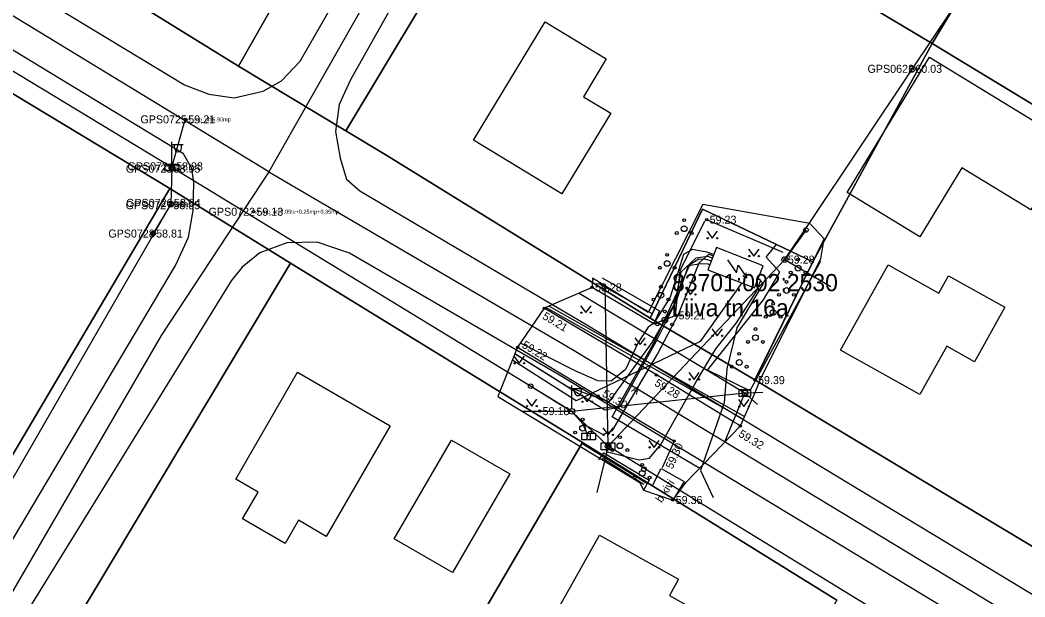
# Model space of a CAD drawing. Extents: x 580119 to 583377, y 6518915 to 6520820.
# Drawn here: x 581772.7 to 581860.5, y 6520226.6 to 6520277 of the extents above; entities that cross this region are included whole.
import ezdxf

# ---------------------------------------------------------------- set-up
doc = ezdxf.new("R2010")
doc.units = 0
for name, color, linetype in [('AED', 7, 'Continuous'), ('ELRAJATISMP', 7, 'Continuous'), ('HALJASTUS', 7, 'Continuous'), ('HOONE', 7, 'Continuous'), ('Hoone Elu- või ühiskondlik hoone', 7, 'Continuous'), ('Hoone Kõrval- või tootmishoone', 7, 'Continuous'), ('KORGUS-EH2000', 7, 'Continuous'), ('KPKAABEL', 7, 'Continuous'), ('KTRASS', 7, 'Continuous'), ('L_AADRESS', 7, 'Continuous'), ('MAAMUDEL', 7, 'Continuous'), ('MOOTKORG-EH2000', 7, 'Continuous'), ('MOOTMPUNKT', 7, 'Continuous'), ('MOOTNR', 7, 'Continuous'), ('MOOTPIIR', 7, 'Continuous'), ('MPKAABEL', 7, 'Continuous'), ('MPOHULIIN', 7, 'Continuous'), ('PIIR', 7, 'Continuous'), ('POST', 7, 'Continuous'), ('PUU', 7, 'Continuous'), ('RAJATIS', 7, 'Continuous'), ('Rippe kõrgus', 7, 'Continuous'), ('SIOHULIIN', 7, 'Continuous'), ('SIRAJATIS', 7, 'Continuous'), ('TEE', 7, 'Continuous'), ('Tee Liiklusala', 7, 'Continuous'), ('Tee Tänav Püsikate', 7, 'Continuous'), ('TUNNUS', 7, 'Continuous'), ('VTRASS', 7, 'Continuous')]:
    doc.layers.add(name, color=color, linetype=linetype)

msp = doc.modelspace()

# ---------------------------------------------------------------- linework, layer by layer
at = {"layer": 'AED'}
msp.add_line((581827.466, 6520236.498), (581821.792, 6520239.985), dxfattribs=at)
for points in [[(581839.378, 6520256.69), (581832.693, 6520259.554)], [(581836.922, 6520245.539), (581840.548, 6520252.925), (581842.98, 6520257.886)]]:
    msp.add_lwpolyline(points, dxfattribs=at)
at = {"layer": 'ELRAJATISMP'}
for p, q in [((581785.791, 6520264.412), (581785.791, 6520263.816)), ((581786.063, 6520264.412), (581786.063, 6520263.816)), ((581822.227, 6520240.919), (581822.227, 6520240.322)), ((581822.499, 6520240.919), (581822.499, 6520240.322)), ((581823.935, 6520240.058), (581823.935, 6520239.461)), ((581824.206, 6520240.058), (581824.206, 6520239.461))]:
    msp.add_line(p, q, dxfattribs=at)
for points in [[(581785.33, 6520264.412), (581786.524, 6520264.412), (581786.524, 6520263.816), (581785.33, 6520263.816)], [(581821.766, 6520240.919), (581822.96, 6520240.919), (581822.96, 6520240.322), (581821.766, 6520240.322)], [(581823.473, 6520240.058), (581824.668, 6520240.058), (581824.668, 6520239.461), (581823.473, 6520239.461)]]:
    msp.add_lwpolyline(points, close=True, dxfattribs=at)
at = {"layer": 'HALJASTUS'}
for p, q in [((581832.722, 6520258.54), (581833.185, 6520257.933)), ((581833.185, 6520257.933), (581833.631, 6520258.54)), ((581836.362, 6520256.984), (581836.825, 6520256.377)), ((581836.825, 6520256.377), (581837.271, 6520256.984)), ((581828.083, 6520250.471), (581822.67, 6520253.641)), ((581827.982, 6520251.297), (581823.284, 6520253.95)), ((581830.823, 6520253.633), (581831.286, 6520253.026)), ((581831.286, 6520253.026), (581831.732, 6520253.633)), ((581821.671, 6520252.042), (581822.134, 6520251.435)), ((581822.134, 6520251.435), (581822.58, 6520252.042)), ((581833.155, 6520250.026), (581833.618, 6520249.419)), ((581833.618, 6520249.419), (581834.064, 6520250.026)), ((581826.406, 6520249.248), (581826.869, 6520248.641)), ((581826.869, 6520248.641), (581827.315, 6520249.248)), ((581815.84, 6520247.621), (581816.304, 6520247.015)), ((581816.304, 6520247.015), (581816.749, 6520247.621)), ((581831.141, 6520246.207), (581831.604, 6520245.6)), ((581831.604, 6520245.6), (581832.05, 6520246.207)), ((581816.936, 6520243.873), (581817.399, 6520243.266)), ((581817.399, 6520243.266), (581817.845, 6520243.873)), ((581821.777, 6520244.262), (581822.24, 6520243.655)), ((581822.24, 6520243.655), (581822.686, 6520244.262)), ((581835.487, 6520243.838), (581835.95, 6520243.231)), ((581835.95, 6520243.231), (581836.396, 6520243.838)), ((581823.614, 6520241.362), (581824.078, 6520240.756)), ((581824.078, 6520240.756), (581824.523, 6520241.362)), ((581827.642, 6520240.266), (581828.106, 6520239.659)), ((581828.106, 6520239.659), (581828.551, 6520240.266)), ((581827.199, 6520236.43), (581823.552, 6520238.734))]:
    msp.add_line(p, q, dxfattribs=at)
for points in [[(581828.083, 6520250.471), (581829.976, 6520251.196), (581830.373, 6520255.128), (581832.537, 6520259.46)], [(581842.643, 6520255.917), (581836.47, 6520244.601), (581832.774, 6520246.407), (581837.658, 6520252.565), (581839.089, 6520254.972), (581837.891, 6520256.288), (581838.778, 6520257.354)], [(581823.56, 6520254.485), (581828.564, 6520251.599), (581828.083, 6520250.471)], [(581823.261, 6520238.588), (581823.694, 6520239.187), (581827.667, 6520236.798), (581827.164, 6520235.94)]]:
    msp.add_lwpolyline(points, dxfattribs=at)
for centre in [(581832.784, 6520257.933), (581833.613, 6520257.933), (581836.424, 6520256.377), (581837.253, 6520256.377), (581830.885, 6520253.026), (581831.714, 6520253.026), (581821.733, 6520251.435), (581822.562, 6520251.435), (581833.217, 6520249.419), (581834.046, 6520249.419), (581826.468, 6520248.641), (581827.297, 6520248.641), (581815.903, 6520247.015), (581816.731, 6520247.015), (581831.203, 6520245.6), (581832.032, 6520245.6), (581816.998, 6520243.266), (581817.827, 6520243.266), (581821.839, 6520243.655), (581822.668, 6520243.655), (581835.549, 6520243.231), (581836.378, 6520243.231), (581823.677, 6520240.756), (581824.505, 6520240.756), (581827.705, 6520239.659), (581828.534, 6520239.659)]:
    msp.add_circle(centre, 0.055, dxfattribs=at)
at = {"layer": 'HOONE'}
for p, q in [((581834.528, 6520256.055), (581835.296, 6520254.925)), ((581835.296, 6520254.925), (581835.439, 6520255.595)), ((581835.439, 6520255.595), (581836.203, 6520254.483)), ((581835.864, 6520254.689), (581836.203, 6520254.483)), ((581836.203, 6520254.483), (581836.148, 6520254.903))]:
    msp.add_line(p, q, dxfattribs=at)
at = {"layer": 'Hoone Elu- või ühiskondlik hoone'}
for points in [[(581824.303, 6520268.845), (581820.036, 6520261.801), (581812.298, 6520266.488), (581818.564, 6520276.833), (581823.908, 6520273.596), (581821.909, 6520270.295)], [(581848.562, 6520255.598), (581852.99, 6520253.13), (581853.842, 6520254.658), (581858.765, 6520251.913), (581856.109, 6520247.148), (581853.689, 6520248.497), (581851.338, 6520244.28), (581844.406, 6520248.144)], [(581805.018, 6520241.546), (581799.427, 6520231.891), (581796.996, 6520233.293), (581795.82, 6520231.264), (581792.106, 6520233.418), (581793.467, 6520235.767), (581791.514, 6520236.901), (581796.918, 6520246.233)], [(581836.336, 6520222.854), (581831.118, 6520213.557), (581817.32, 6520221.3), (581823.333, 6520232.009), (581830.215, 6520228.148), (581829.428, 6520226.73)]]:
    msp.add_lwpolyline(points, close=True, dxfattribs=at)
at = {"layer": 'Hoone Kõrval- või tootmishoone'}
for points in [[(581864.55, 6520266.195), (581861.03, 6520260.418), (581855.004, 6520264.091), (581851.329, 6520258.061), (581844.973, 6520261.934), (581852.169, 6520273.74)], [(581805.375, 6520231.681), (581810.374, 6520240.306), (581815.479, 6520237.349), (581810.48, 6520228.726)]]:
    msp.add_lwpolyline(points, close=True, dxfattribs=at)
at = {"layer": 'KORGUS-EH2000'}
for centre in [(581832.693, 6520259.554), (581839.53, 6520256.065), (581822.67, 6520253.641), (581818.485, 6520251.819), (581829.976, 6520251.196), (581816.164, 6520248.415), (581828.301, 6520245.992), (581836.922, 6520245.539), (581823.181, 6520244.154), (581818.085, 6520242.831), (581835.637, 6520241.537), (581829.849, 6520240.211), (581829.725, 6520235.067)]:
    msp.add_circle(centre, 0.1, dxfattribs=at)
at = {"layer": 'KPKAABEL'}
for points in [[(581832.09, 6520237.828), (581824.438, 6520242.332), (581828.156, 6520248.945), (581831.258, 6520255.664), (581832.008, 6520256.121), (581832.594, 6520256.098), (581833.114, 6520255.966)], [(581835.762, 6520254.025), (581832.124, 6520248.9), (581821.294, 6520243.721), (581815.71, 6520247.284)]]:
    msp.add_lwpolyline(points, dxfattribs=at)
at = {"layer": 'KTRASS'}
msp.add_line((581818.912, 6520252.004), (581836, 6520242.348), dxfattribs=at)
at = {"layer": 'MOOTMPUNKT'}
for centre in [(581850.68, 6520272.732), (581787.097, 6520268.317), (581785.822, 6520264.01), (581786.033, 6520264.218), (581785.8, 6520260.82), (581785.844, 6520261.02), (581793.059, 6520260.246), (581784.288, 6520258.342)]:
    msp.add_circle(centre, 0.1, dxfattribs=at)
at = {"layer": 'MOOTPIIR'}
msp.add_lwpolyline([(581822.67, 6520253.641), (581818.485, 6520251.819), (581816.164, 6520248.415), (581814.433, 6520244.097), (581826.858, 6520236.585), (581827.164, 6520235.94), (581829.725, 6520235.067), (581830.914, 6520236.63), (581835.637, 6520241.537), (581836.938, 6520244.448), (581837.461, 6520245.756), (581842.672, 6520256.148), (581842.98, 6520257.886), (581841.725, 6520259.214), (581832.36, 6520260.889), (581827.587, 6520251.444), (581822.704, 6520254.435)], close=True, dxfattribs=at)
at = {"layer": 'MPKAABEL'}
msp.add_line((581821.871, 6520241.723), (581820.901, 6520242.813), dxfattribs=at)
for points in [[(581833.2, 6520256.185), (581832.797, 6520256.348), (581831.754, 6520256.195), (581830.426, 6520254.984), (581829.867, 6520252.203), (581827.906, 6520248.824), (581824.148, 6520243.645), (581820.508, 6520244.957), (581815.93, 6520247.831)], [(581833.329, 6520256.518), (581832.719, 6520256.715), (581831.43, 6520256.953), (581830.664, 6520256.504), (581829.496, 6520252.773), (581828.059, 6520250.527), (581827.57, 6520250.152), (581826.699, 6520248.828), (581825.598, 6520246.465), (581824.328, 6520245.453), (581823.18, 6520245.465), (581821.254, 6520246.32), (581816.41, 6520248.776)], [(581822.363, 6520240.621), (581821.871, 6520241.723), (581823.648, 6520240.801), (581824.453, 6520241.133), (581828.398, 6520247.82), (581830.262, 6520251.371), (581832.039, 6520255.789), (581832.875, 6520256.555), (581833.278, 6520256.388)], [(581815.934, 6520247.84), (581821.098, 6520244.609), (581823.789, 6520242.93), (581825.086, 6520243.203), (581828.262, 6520248.906), (581830.047, 6520252.453), (581831.105, 6520255.547), (581832.172, 6520255.738), (581832.781, 6520255.684), (581832.976, 6520255.608)], [(581837.215, 6520254.426), (581837.621, 6520253.973), (581835.32, 6520250.113), (581834.453, 6520246.527), (581834.234, 6520243.559), (581832.145, 6520237.648), (581833.27, 6520235.277)], [(581824.071, 6520239.759), (581823.906, 6520239.316), (581826.789, 6520238.566), (581827.695, 6520238.734), (581828.688, 6520239.93), (581831.809, 6520245.457), (581833.484, 6520248.273), (581835.297, 6520250.539), (581837.07, 6520253.344), (581837.43, 6520254.273), (581837.191, 6520254.365)]]:
    msp.add_lwpolyline(points, dxfattribs=at)
at = {"layer": 'MPOHULIIN'}
for p, q in [((581785.927, 6520264.114), (581787.097, 6520268.317)), ((581839.53, 6520256.065), (581824.071, 6520239.759)), ((581839.53, 6520256.065), (581843.539, 6520253.717)), ((581824.071, 6520239.759), (581823.805, 6520253.76)), ((581818.085, 6520242.831), (581820.901, 6520242.813)), ((581824.071, 6520239.759), (581820.901, 6520242.813))]:
    msp.add_line(p, q, dxfattribs=at)
for points in [[(581815.289, 6520246.232), (581785.927, 6520264.114), (581748.774, 6520286.579), (581716.955, 6520305.703), (581694.046, 6520319.434)], [(581841.646, 6520259.228), (581850.68, 6520272.732), (581867.762, 6520298.217)], [(581785.927, 6520264.114), (581785.822, 6520260.92), (581761.898, 6520219.504), (581760.006, 6520194.701), (581760.577, 6520193.807)], [(581839.53, 6520256.065), (581841.646, 6520259.228)], [(581820.901, 6520242.813), (581815.289, 6520246.232)], [(581830.36, 6520235.901), (581824.071, 6520239.759), (581823.075, 6520235.724)], [(582074.165, 6520090.199), (582035.134, 6520113.983), (581994.066, 6520138.741), (581958.895, 6520159.666), (581929.453, 6520177.381), (581899.05, 6520195.285), (581871.107, 6520211.349), (581850.55, 6520223.515), (581830.36, 6520235.901)]]:
    msp.add_lwpolyline(points, dxfattribs=at)
at = {"layer": 'PIIR'}
for points in [[(581641.44, 6520358.2), (581663.75, 6520346.68), (581696.78, 6520330.58), (581710.47, 6520322.41), (581741.73, 6520303.41), (581773.45, 6520284.3), (581791.76, 6520272.95), (581801.15, 6520267.32), (581804.72, 6520265.17), (581827.76, 6520250.96), (581836.91, 6520245.57), (581863.22, 6520229.79), (581868.94, 6520226.76), (581900.21, 6520207.51)], [(581844.07, 6520226.32), (581821.83, 6520240.08), (581796.29, 6520255.75), (581785.75, 6520262.28), (581756.8, 6520279.75), (581732.4, 6520294.58), (581704.08, 6520311.14), (581691.15, 6520319.03), (581661.06, 6520334.72)]]:
    msp.add_lwpolyline(points, dxfattribs=at)
for points in [[(581801.15, 6520267.32), (581791.76, 6520272.95), (581808.12, 6520301.74), (581821.48, 6520324.8), (581832.08, 6520318.73), (581818.12, 6520295.6)], [(581788.16, 6520313.33), (581791.12, 6520311.82), (581808.12, 6520301.74), (581791.76, 6520272.95), (581773.45, 6520284.3)], [(581849.2, 6520308.51), (581866.2, 6520297.82), (581852.4, 6520274.95), (581835.18, 6520285.22)], [(581866.2, 6520297.82), (581884.83, 6520286.51), (581870.83, 6520263.78), (581852.4, 6520274.95)], [(581818.12, 6520295.6), (581835.18, 6520285.22), (581852.4, 6520274.95), (581841.97, 6520255.88), (581832.33, 6520260.46), (581827.76, 6520250.96), (581804.72, 6520265.17), (581801.15, 6520267.32)], [(581756.8, 6520279.75), (581785.75, 6520262.28), (581768.66, 6520233.42), (581739.56, 6520251.04)], [(581841.97, 6520255.88), (581852.4, 6520274.95), (581870.83, 6520263.78), (581886.05, 6520254.56), (581863.22, 6520229.79), (581836.91, 6520245.57)], [(581696.38, 6520086.78), (581684.97, 6520093.06), (581699.34, 6520117.41), (581709.83, 6520135.06), (581730.99, 6520170.6), (581750.36, 6520203.28), (581768.66, 6520233.42), (581785.75, 6520262.28), (581796.29, 6520255.75), (581771.2, 6520213.92), (581755.98, 6520188.75), (581745.76, 6520171.44), (581728.54, 6520142.46), (581721.29, 6520129.05)], [(581832.33, 6520260.46), (581841.97, 6520255.88), (581836.91, 6520245.57), (581827.76, 6520250.96)], [(581796.29, 6520255.75), (581821.83, 6520240.08), (581802.53, 6520207.1), (581797.51, 6520198.44), (581771.2, 6520213.92)], [(581821.83, 6520240.08), (581844.07, 6520226.32), (581828.18, 6520198.39), (581825.04, 6520199.93), (581822.65, 6520196.25), (581820.67, 6520197.28), (581802.53, 6520207.1)]]:
    msp.add_lwpolyline(points, close=True, dxfattribs=at)
at = {"layer": 'POST'}
for p, q in [((581785.927, 6520264.364), (581785.927, 6520266.364)), ((581785.927, 6520266.114), (581786.927, 6520266.114)), ((581786.154, 6520265.793), (581786.154, 6520266.114)), ((581786.767, 6520265.793), (581786.767, 6520266.114)), ((581785.927, 6520264.114), (581785.927, 6520264.114)), ((581820.901, 6520243.063), (581820.901, 6520245.063)), ((581820.901, 6520244.813), (581821.901, 6520244.813)), ((581821.128, 6520244.492), (581821.128, 6520244.813)), ((581821.741, 6520244.492), (581821.741, 6520244.813)), ((581820.901, 6520242.813), (581820.901, 6520242.813))]:
    msp.add_line(p, q, dxfattribs=at)
for points in [[(581785.822, 6520260.92), (581784.288, 6520258.342)], [(581841.383, 6520258.655), (581839.53, 6520256.065)], [(581817.303, 6520245.014), (581820.901, 6520242.813)]]:
    msp.add_lwpolyline(points, dxfattribs=at)
for centre, radius in [((581850.68, 6520272.732), 0.25), ((581785.927, 6520264.114), 0.25), ((581785.822, 6520260.92), 0.25), ((581841.383, 6520258.655), 0.2), ((581784.288, 6520258.342), 0.2), ((581839.53, 6520256.065), 0.25), ((581817.303, 6520245.014), 0.2), ((581836.033, 6520244.413), 0.25), ((581820.901, 6520242.813), 0.25), ((581824.071, 6520239.759), 0.25), ((581827.203, 6520237.753), 0.2)]:
    msp.add_circle(centre, radius, dxfattribs=at)
for centre in [(581786.46, 6520265.793), (581821.434, 6520244.492)]:
    msp.add_arc(centre, 0.306, 180, 0, dxfattribs=at)
at = {"layer": 'PUU'}
for centre, radius in [((581830.727, 6520258.766), 0.25), ((581830.727, 6520259.516), 0.125), ((581830.077, 6520258.391), 0.125), ((581831.377, 6520258.391), 0.125), ((581829.242, 6520256.482), 0.125), ((581840.692, 6520256.068), 0.125), ((581828.592, 6520255.357), 0.125), ((581829.242, 6520255.732), 0.25), ((581829.892, 6520255.357), 0.125), ((581840.692, 6520255.318), 0.25), ((581840.042, 6520254.943), 0.125), ((581841.342, 6520254.943), 0.125), ((581828.691, 6520253.702), 0.125), ((581839.674, 6520253.366), 0.25), ((581839.674, 6520254.116), 0.125), ((581828.041, 6520252.577), 0.125), ((581828.691, 6520252.952), 0.25), ((581829.341, 6520252.577), 0.125), ((581839.024, 6520252.991), 0.125), ((581840.324, 6520252.991), 0.125), ((581838.508, 6520252.206), 0.125), ((581829.029, 6520250.772), 0.25), ((581829.029, 6520251.522), 0.125), ((581837.858, 6520251.081), 0.125), ((581838.508, 6520251.456), 0.25), ((581839.158, 6520251.081), 0.125), ((581828.379, 6520250.397), 0.125), ((581829.679, 6520250.397), 0.125), ((581836.96, 6520250), 0.125), ((581836.96, 6520249.25), 0.25), ((581836.31, 6520248.875), 0.125), ((581837.61, 6520248.875), 0.125), ((581835.54, 6520247.835), 0.125), ((581834.89, 6520246.71), 0.125), ((581835.54, 6520247.085), 0.25), ((581836.19, 6520246.71), 0.125), ((581821.841, 6520242.087), 0.125), ((581821.841, 6520241.337), 0.25), ((581821.191, 6520240.962), 0.125), ((581822.491, 6520240.962), 0.125), ((581825.11, 6520240.553), 0.125), ((581824.46, 6520239.428), 0.125), ((581825.11, 6520239.803), 0.25), ((581825.76, 6520239.428), 0.125), ((581827.05, 6520238.146), 0.125), ((581826.4, 6520237.021), 0.125), ((581827.05, 6520237.396), 0.25), ((581827.7, 6520237.021), 0.125)]:
    msp.add_circle(centre, radius, dxfattribs=at)
at = {"layer": 'RAJATIS'}
msp.add_lwpolyline([(581832.806, 6520255.173), (581836.889, 6520253.587), (581837.646, 6520255.534), (581833.563, 6520257.12)], close=True, dxfattribs=at)
at = {"layer": 'SIOHULIIN'}
msp.add_line((581836.033, 6520244.413), (581821.546, 6520253.116), dxfattribs=at)
for points in [[(581837.59, 6520244.473), (581836.033, 6520244.413), (581820.901, 6520242.813), (581816.592, 6520242.794)], [(581834.293, 6520240.141), (581836.033, 6520244.413), (581837.142, 6520243.397)]]:
    msp.add_lwpolyline(points, dxfattribs=at)
at = {"layer": 'SIRAJATIS'}
msp.add_lwpolyline([(581835.533, 6520244.713), (581836.533, 6520244.713), (581836.533, 6520244.113), (581835.533, 6520244.113)], close=True, dxfattribs=at)
for centre, radius in [((581835.833, 6520244.413), 0.0304), ((581835.833, 6520244.413), 0.029), ((581835.833, 6520244.413), 0.0277), ((581835.833, 6520244.413), 0.0263), ((581835.833, 6520244.413), 0.0249), ((581835.833, 6520244.413), 0.0236), ((581835.833, 6520244.413), 0.0222), ((581835.833, 6520244.413), 0.0209), ((581835.833, 6520244.413), 0.0195), ((581835.833, 6520244.413), 0.0181), ((581835.833, 6520244.413), 0.0168), ((581835.833, 6520244.413), 0.0154), ((581835.833, 6520244.413), 0.014), ((581835.833, 6520244.413), 0.0127), ((581835.833, 6520244.413), 0.0113), ((581835.833, 6520244.413), 0.00996), ((581835.833, 6520244.413), 0.0086), ((581835.833, 6520244.413), 0.00724), ((581835.833, 6520244.413), 0.00587), ((581835.833, 6520244.413), 0.00451), ((581835.833, 6520244.413), 0.00315), ((581835.833, 6520244.413), 0.00179), ((581835.833, 6520244.413), 0.000426), ((581836.233, 6520244.413), 0.0304), ((581836.233, 6520244.413), 0.029), ((581836.233, 6520244.413), 0.0277), ((581836.233, 6520244.413), 0.0263), ((581836.233, 6520244.413), 0.0249), ((581836.233, 6520244.413), 0.0236), ((581836.233, 6520244.413), 0.0222), ((581836.233, 6520244.413), 0.0209), ((581836.233, 6520244.413), 0.0195), ((581836.233, 6520244.413), 0.0181), ((581836.233, 6520244.413), 0.0168), ((581836.233, 6520244.413), 0.0154), ((581836.233, 6520244.413), 0.014), ((581836.233, 6520244.413), 0.0127), ((581836.233, 6520244.413), 0.0113), ((581836.233, 6520244.413), 0.00996), ((581836.233, 6520244.413), 0.0086), ((581836.233, 6520244.413), 0.00724), ((581836.233, 6520244.413), 0.00587), ((581836.233, 6520244.413), 0.00451), ((581836.233, 6520244.413), 0.00315), ((581836.233, 6520244.413), 0.00179), ((581836.233, 6520244.413), 0.000426)]:
    msp.add_circle(centre, radius, dxfattribs=at)
at = {"layer": 'TEE'}
for points in [[(581835.637, 6520241.537), (581834.893, 6520241.982), (581828.301, 6520245.992), (581818.485, 6520251.819)], [(581816.164, 6520248.415), (581823.181, 6520244.154), (581829.849, 6520240.211), (581828.811, 6520237.865)], [(581827.942, 6520236.349), (581828.708, 6520237.831), (581830.727, 6520236.68), (581829.725, 6520235.067)]]:
    msp.add_lwpolyline(points, dxfattribs=at)
at = {"layer": 'Tee Liiklusala'}
for points in [[(581708.973, 6520318.471), (581787.026, 6520271.325), (581789.162, 6520270.507), (581791.383, 6520270.184), (581793.899, 6520270.794), (581795.507, 6520271.692), (581797.15, 6520273.396), (581823.944, 6520319.987), (581823.993, 6520323.124), (581823.536, 6520325.218), (581786.005, 6520348.211), (581807.901, 6520386.495)], [(581883.73, 6520290.39), (581831.98, 6520320.646), (581829.373, 6520319.902), (581827.47, 6520317.82), (581801.546, 6520271.778), (581800.552, 6520269.623), (581800.234, 6520267.264), (581800.633, 6520264.933), (581801.205, 6520263.087), (581802.352, 6520262.069), (581822.226, 6520250.366), (581872.961, 6520219.702)], [(581731.837, 6520164.161), (581786.238, 6520255.548), (581787.379, 6520258.039), (581787.79, 6520260.355), (581787.852, 6520262.801), (581787.679, 6520264.028), (581786.951, 6520265.31), (581705.974, 6520314.449), (581704.17, 6520314.706), (581703.094, 6520314.493), (581701.329, 6520313.616), (581699.897, 6520312.338), (581698.216, 6520309.539), (581693.916, 6520301.695), (581686.241, 6520286.444), (581655.639, 6520225.534)], [(581870.379, 6520215.42), (581819.672, 6520246.068), (581801.473, 6520256.64), (581798.624, 6520257.596), (581795.966, 6520257.527), (581793.622, 6520256.656), (581792.071, 6520255.4), (581791.12, 6520254.216), (581773.627, 6520225.912)]]:
    msp.add_lwpolyline(points, dxfattribs=at)
at = {"layer": 'Tee Tänav Püsikate'}
for points in [[(581829.397, 6520325.257), (581794.4, 6520263.722)], [(581794.4, 6520263.722), (581700.795, 6520320.678)], [(581794.4, 6520263.722), (581784.992, 6520249.451), (581771.905, 6520226.93), (581733.57, 6520163.162), (581718.97, 6520136.732)], [(581794.4, 6520263.722), (581820.949, 6520248.217), (581871.67, 6520217.561), (581904.384, 6520197.949)]]:
    msp.add_lwpolyline(points, dxfattribs=at)
at = {"layer": 'VTRASS'}
msp.add_line((581835.897, 6520242.119), (581818.625, 6520251.879), dxfattribs=at)

# ---------------------------------------------------------------- texts
at = {"layer": 'KORGUS-EH2000'}
for s, p in [(' 59.23', (581832.693, 6520259.204)), (' 59.28', (581839.53, 6520255.715)), (' 59.28', (581822.67, 6520253.291)), (' 59.21', (581829.976, 6520250.846)), (' 59.39', (581836.922, 6520245.189)), (' 59.18', (581818.085, 6520242.481)), (' 59.36', (581829.725, 6520234.717))]:
    msp.add_text(s, height=0.7, dxfattribs=at).set_placement(p)
for s, rotation, p in [(' 59.21', 329.30671, (581818.039, 6520251.066)), (' 59.22', 328.73439, (581816.255, 6520248.564)), (' 59.28', 328.68678, (581827.846, 6520245.244)), (' 59.30', 329.40109, (581823.27, 6520244.305)), (' 59.32', 329.14734, (581835.188, 6520240.786)), (' 59.30', 66.14568, (581829.597, 6520237.479))]:
    msp.add_text(s, height=0.7, rotation=rotation, dxfattribs=at).set_placement(p)
at = {"layer": 'L_AADRESS'}
msp.add_text('Liiva tn 16a', height=1.5, dxfattribs=at).set_placement((581829.602, 6520251.103))
at = {"layer": 'MAAMUDEL'}
for p in [(581785.8, 6520260.645), (581785.844, 6520260.845)]:
    msp.add_text(' kaabel', height=0.35, dxfattribs=at).set_placement(p)
at = {"layer": 'MOOTKORG-EH2000'}
for s, p in [(' 60.03', (581850.68, 6520272.382)), (' 59.21', (581787.097, 6520267.968)), (' 58.95', (581785.822, 6520263.66)), (' 58.98', (581786.033, 6520263.868)), (' 58.85', (581785.8, 6520260.47)), (' 58.84', (581785.844, 6520260.67)), (' 59.13', (581793.059, 6520259.896)), (' 58.81', (581784.288, 6520257.992))]:
    msp.add_text(s, height=0.7, dxfattribs=at).set_placement(p)
at = {"layer": 'MOOTNR'}
for s, p in [('GPS0622 ', (581846.761, 6520272.382)), ('GPS0725 ', (581783.178, 6520267.968)), ('GPS0723 ', (581781.902, 6520263.66)), ('GPS0724 ', (581782.043, 6520263.868)), ('GPS0727 ', (581781.88, 6520260.47)), ('GPS0726 ', (581781.924, 6520260.67)), ('GPS0722 ', (581789.139, 6520259.896)), ('GPS0728 ', (581780.368, 6520257.992))]:
    msp.add_text(s, height=0.7, dxfattribs=at).set_placement(p)
at = {"layer": 'Rippe kõrgus'}
for s, p in [(' el_mp_ohl6.90mp', (581787.097, 6520268.143)), (' el_mp_ohl7.05tv+0.25mp+0.35mp', (581793.059, 6520260.071))]:
    msp.add_text(s, height=0.35, dxfattribs=at).set_placement(p)
at = {"layer": 'TEE'}
for s, rotation, p in [('A', 325.13411, (581826.062, 6520244.59)), ('b kivi', 57.00038, (581828.754, 6520234.777))]:
    msp.add_text(s, height=0.7, rotation=rotation, dxfattribs=at).set_placement(p)
at = {"layer": 'TUNNUS'}
msp.add_text('83701:002:2530', height=1.5, dxfattribs=at).set_placement((581829.665, 6520253.308))

doc.saveas('drawing.dxf')
